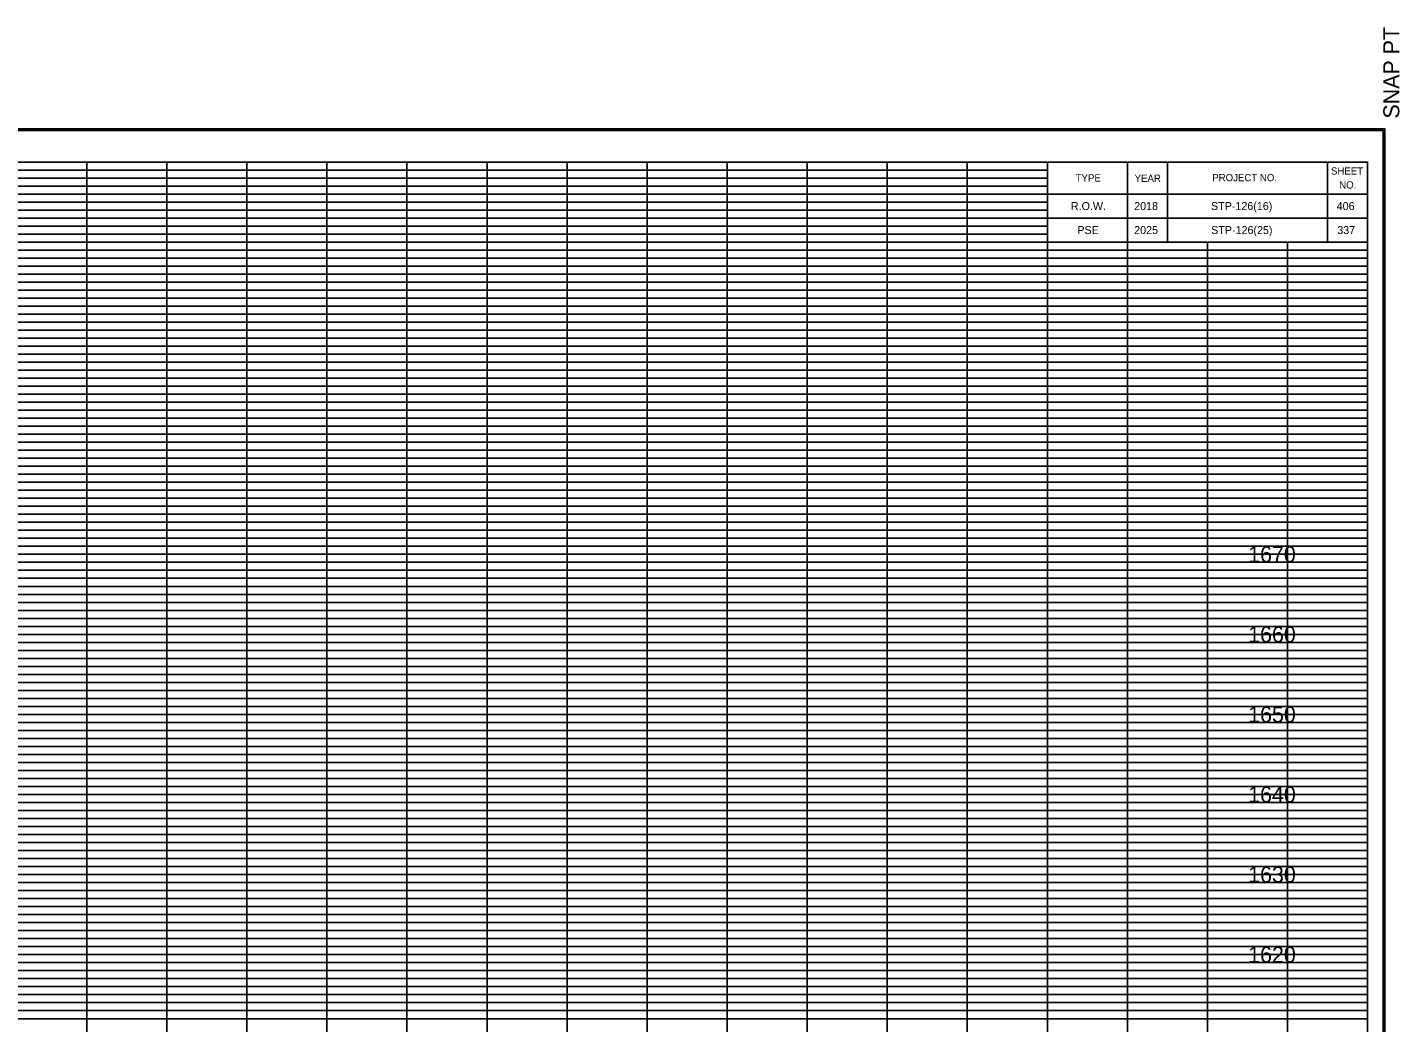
# Model space of a CAD drawing. Extents: x 980 to 1380, y 1248 to 3387.
# Drawn here: x 1152.6 to 1324, y 2452.5 to 2576.8 of the extents above; entities that cross this region are included whole.
import ezdxf

# ---------------------------------------------------------------- set-up
doc = ezdxf.new("R2010")
doc.units = 0
for name, color, linetype in [('DESIGN - SCRATCH - User 1', 7, 'Continuous'), ('DESIGN - SHEET - Corner Text', 7, 'Continuous'), ('DESIGN - SHEET - Light Grid', 7, 'Continuous'), ('DESIGN - SHEET - Linework', 7, 'Continuous'), ('DESIGN - SHEET - Plot Shape', 7, 'Continuous'), ('DESIGN - TYPICAL - Text', 7, 'Continuous')]:
    doc.layers.add(name, color=color, linetype=linetype)

# ---------------------------------------------------------------- blocks, each defined once
blk = doc.blocks.new('XSTSHT')
at = {"layer": 'DESIGN - SCRATCH - User 1'}
for p, q in [((28.5, 20.45), (28.5, 20.45)), ((29.24, 20.45), (29.24, 20.45)), ((30.49, 20.45), (30.49, 20.45)), ((31.74, 20.45), (31.74, 20.45)), ((28.5, 20.15), (28.5, 20.15)), ((29.24, 20.15), (29.24, 20.15)), ((30.49, 20.15), (30.49, 20.15)), ((31.74, 20.15), (31.74, 20.15))]:
    blk.add_line(p, q, dxfattribs=at)
at = {"layer": 'DESIGN - SHEET - Light Grid'}
for p, q in [((8, 20.9), (16, 20.9)), ((8, 20.8), (16, 20.8)), ((16, 20.9), (24, 20.9)), ((16, 20.8), (24, 20.8)), ((24, 20.9), (28, 20.9)), ((24, 20.8), (28, 20.8)), ((8, 20.7), (16, 20.7)), ((8, 20.6), (16, 20.6)), ((16, 20.7), (24, 20.7)), ((16, 20.6), (24, 20.6)), ((24, 20.7), (28, 20.7)), ((24, 20.6), (28, 20.6)), ((8, 20.5), (16, 20.5)), ((8, 20.4), (16, 20.4)), ((16, 20.5), (24, 20.5)), ((16, 20.4), (24, 20.4)), ((24, 20.5), (28, 20.5)), ((24, 20.4), (28, 20.4)), ((8, 20.3), (16, 20.3)), ((16, 20.3), (24, 20.3)), ((24, 20.3), (28, 20.3)), ((8, 20.2), (16, 20.2)), ((8, 20.1), (16, 20.1)), ((16, 20.2), (24, 20.2)), ((16, 20.1), (24, 20.1)), ((24, 20.2), (28, 20.2)), ((24, 20.1), (28, 20.1)), ((8, 19.9), (16, 19.9)), ((16, 19.9), (24, 19.9)), ((24, 19.9), (32, 19.9)), ((8, 19.8), (16, 19.8)), ((16, 19.8), (24, 19.8)), ((24, 19.8), (32, 19.8)), ((8, 19.7), (16, 19.7)), ((8, 19.6), (16, 19.6)), ((16, 19.7), (24, 19.7)), ((16, 19.6), (24, 19.6)), ((24, 19.7), (32, 19.7)), ((24, 19.6), (32, 19.6)), ((8, 19.5), (16, 19.5)), ((8, 19.4), (16, 19.4)), ((16, 19.5), (24, 19.5)), ((16, 19.4), (24, 19.4)), ((24, 19.5), (32, 19.5)), ((24, 19.4), (32, 19.4)), ((8, 19.3), (16, 19.3)), ((8, 19.2), (16, 19.2)), ((16, 19.3), (24, 19.3)), ((16, 19.2), (24, 19.2)), ((24, 19.3), (32, 19.3)), ((24, 19.2), (32, 19.2)), ((8, 19.1), (16, 19.1)), ((16, 19.1), (24, 19.1)), ((24, 19.1), (32, 19.1)), ((8, 18.9), (16, 18.9)), ((16, 18.9), (24, 18.9)), ((24, 18.9), (32, 18.9)), ((8, 18.8), (16, 18.8)), ((8, 18.7), (16, 18.7)), ((16, 18.8), (24, 18.8)), ((16, 18.7), (24, 18.7)), ((24, 18.8), (32, 18.8)), ((24, 18.7), (32, 18.7)), ((8, 18.6), (16, 18.6)), ((16, 18.6), (24, 18.6)), ((24, 18.6), (32, 18.6)), ((8, 18.5), (16, 18.5)), ((8, 18.4), (16, 18.4)), ((16, 18.5), (24, 18.5)), ((16, 18.4), (24, 18.4)), ((24, 18.5), (32, 18.5)), ((24, 18.4), (32, 18.4)), ((8, 18.3), (16, 18.3)), ((8, 18.2), (16, 18.2)), ((16, 18.3), (24, 18.3)), ((16, 18.2), (24, 18.2)), ((24, 18.3), (32, 18.3)), ((24, 18.2), (32, 18.2)), ((8, 18.1), (16, 18.1)), ((16, 18.1), (24, 18.1)), ((24, 18.1), (32, 18.1)), ((8, 17.9), (16, 17.9)), ((16, 17.9), (24, 17.9)), ((24, 17.9), (32, 17.9)), ((8, 17.8), (16, 17.8)), ((8, 17.7), (16, 17.7)), ((16, 17.8), (24, 17.8)), ((16, 17.7), (24, 17.7)), ((24, 17.8), (32, 17.8)), ((24, 17.7), (32, 17.7)), ((8, 17.6), (16, 17.6)), ((8, 17.5), (16, 17.5)), ((16, 17.6), (24, 17.6)), ((16, 17.5), (24, 17.5)), ((24, 17.6), (32, 17.6)), ((24, 17.5), (32, 17.5)), ((8, 17.4), (16, 17.4)), ((16, 17.4), (24, 17.4)), ((24, 17.4), (32, 17.4)), ((8, 17.3), (16, 17.3)), ((8, 17.2), (16, 17.2)), ((16, 17.3), (24, 17.3)), ((16, 17.2), (24, 17.2)), ((24, 17.3), (32, 17.3)), ((24, 17.2), (32, 17.2)), ((8, 17.1), (16, 17.1)), ((16, 17.1), (24, 17.1)), ((24, 17.1), (32, 17.1)), ((8, 16.9), (16, 16.9)), ((8, 16.8), (16, 16.8)), ((16, 16.9), (24, 16.9)), ((16, 16.8), (24, 16.8)), ((24, 16.9), (32, 16.9)), ((24, 16.8), (32, 16.8)), ((8, 16.7), (16, 16.7)), ((16, 16.7), (24, 16.7)), ((24, 16.7), (32, 16.7)), ((8, 16.6), (16, 16.6)), ((8, 16.5), (16, 16.5)), ((16, 16.6), (24, 16.6)), ((16, 16.5), (24, 16.5)), ((24, 16.6), (32, 16.6)), ((24, 16.5), (32, 16.5)), ((8, 16.4), (16, 16.4)), ((8, 16.3), (16, 16.3)), ((16, 16.4), (24, 16.4)), ((16, 16.3), (24, 16.3)), ((24, 16.4), (32, 16.4)), ((24, 16.3), (32, 16.3)), ((8, 16.2), (16, 16.2)), ((16, 16.2), (24, 16.2)), ((24, 16.2), (32, 16.2)), ((8, 16.1), (16, 16.1)), ((16, 16.1), (24, 16.1)), ((24, 16.1), (32, 16.1)), ((8, 15.9), (16, 15.9)), ((8, 15.8), (16, 15.8)), ((16, 15.9), (24, 15.9)), ((16, 15.8), (24, 15.8)), ((24, 15.9), (32, 15.9)), ((24, 15.8), (32, 15.8)), ((8, 15.7), (16, 15.7)), ((8, 15.6), (16, 15.6)), ((16, 15.7), (24, 15.7)), ((16, 15.6), (24, 15.6)), ((24, 15.7), (32, 15.7)), ((24, 15.6), (32, 15.6)), ((8, 15.5), (16, 15.5)), ((16, 15.5), (24, 15.5)), ((24, 15.5), (32, 15.5)), ((8, 15.4), (16, 15.4)), ((8, 15.3), (16, 15.3)), ((16, 15.4), (24, 15.4)), ((16, 15.3), (24, 15.3)), ((24, 15.4), (32, 15.4)), ((24, 15.3), (32, 15.3)), ((8, 15.2), (16, 15.2)), ((8, 15.1), (16, 15.1)), ((16, 15.2), (24, 15.2)), ((16, 15.1), (24, 15.1)), ((24, 15.2), (32, 15.2)), ((24, 15.1), (32, 15.1)), ((8, 14.9), (16, 14.9)), ((8, 14.8), (16, 14.8)), ((16, 14.9), (24, 14.9)), ((16, 14.8), (24, 14.8)), ((24, 14.9), (32, 14.9)), ((24, 14.8), (32, 14.8)), ((8, 14.7), (16, 14.7)), ((8, 14.6), (16, 14.6)), ((16, 14.7), (24, 14.7)), ((16, 14.6), (24, 14.6)), ((24, 14.7), (32, 14.7)), ((24, 14.6), (32, 14.6)), ((8, 14.5), (16, 14.5)), ((8, 14.4), (16, 14.4)), ((16, 14.5), (24, 14.5)), ((16, 14.4), (24, 14.4)), ((24, 14.5), (32, 14.5)), ((24, 14.4), (32, 14.4)), ((8, 14.3), (16, 14.3)), ((16, 14.3), (24, 14.3)), ((24, 14.3), (32, 14.3)), ((8, 14.2), (16, 14.2)), ((8, 14.1), (16, 14.1)), ((16, 14.2), (24, 14.2)), ((16, 14.1), (24, 14.1)), ((24, 14.2), (32, 14.2)), ((24, 14.1), (32, 14.1)), ((8, 13.9), (16, 13.9)), ((16, 13.9), (24, 13.9)), ((24, 13.9), (32, 13.9)), ((8, 13.8), (16, 13.8)), ((16, 13.8), (24, 13.8)), ((24, 13.8), (32, 13.8)), ((8, 13.7), (16, 13.7)), ((8, 13.6), (16, 13.6)), ((16, 13.7), (24, 13.7)), ((16, 13.6), (24, 13.6)), ((24, 13.7), (32, 13.7)), ((24, 13.6), (32, 13.6)), ((8, 13.5), (16, 13.5)), ((8, 13.4), (16, 13.4)), ((16, 13.5), (24, 13.5)), ((16, 13.4), (24, 13.4)), ((24, 13.5), (32, 13.5)), ((24, 13.4), (32, 13.4)), ((8, 13.3), (16, 13.3)), ((8, 13.2), (16, 13.2)), ((16, 13.3), (24, 13.3)), ((16, 13.2), (24, 13.2)), ((24, 13.3), (32, 13.3)), ((24, 13.2), (32, 13.2)), ((8, 13.1), (16, 13.1)), ((16, 13.1), (24, 13.1)), ((24, 13.1), (32, 13.1)), ((8, 12.9), (16, 12.9)), ((16, 12.9), (24, 12.9)), ((24, 12.9), (32, 12.9)), ((8, 12.8), (16, 12.8)), ((8, 12.7), (16, 12.7)), ((16, 12.8), (24, 12.8)), ((16, 12.7), (24, 12.7)), ((24, 12.8), (32, 12.8)), ((24, 12.7), (32, 12.7)), ((8, 12.6), (16, 12.6)), ((16, 12.6), (24, 12.6)), ((24, 12.6), (32, 12.6)), ((8, 12.5), (16, 12.5)), ((8, 12.4), (16, 12.4)), ((16, 12.5), (24, 12.5)), ((16, 12.4), (24, 12.4)), ((24, 12.5), (32, 12.5)), ((24, 12.4), (32, 12.4)), ((8, 12.3), (16, 12.3)), ((8, 12.2), (16, 12.2)), ((16, 12.3), (24, 12.3)), ((16, 12.2), (24, 12.2)), ((24, 12.3), (32, 12.3)), ((24, 12.2), (32, 12.2)), ((8, 12.1), (16, 12.1)), ((16, 12.1), (24, 12.1)), ((24, 12.1), (32, 12.1)), ((8, 11.9), (16, 11.9)), ((16, 11.9), (24, 11.9)), ((24, 11.9), (32, 11.9)), ((8, 11.8), (16, 11.8)), ((8, 11.7), (16, 11.7)), ((16, 11.8), (24, 11.8)), ((16, 11.7), (24, 11.7)), ((24, 11.8), (32, 11.8)), ((24, 11.7), (32, 11.7)), ((8, 11.6), (16, 11.6)), ((8, 11.5), (16, 11.5)), ((16, 11.6), (24, 11.6)), ((16, 11.5), (24, 11.5)), ((24, 11.6), (32, 11.6)), ((24, 11.5), (32, 11.5)), ((8, 11.4), (16, 11.4)), ((16, 11.4), (24, 11.4)), ((24, 11.4), (32, 11.4)), ((8, 11.3), (16, 11.3)), ((8, 11.2), (16, 11.2)), ((16, 11.3), (24, 11.3)), ((16, 11.2), (24, 11.2)), ((24, 11.3), (32, 11.3)), ((24, 11.2), (32, 11.2)), ((8, 11.1), (16, 11.1)), ((16, 11.1), (24, 11.1)), ((24, 11.1), (32, 11.1)), ((8, 10.9), (16, 10.9)), ((8, 10.8), (16, 10.8)), ((16, 10.9), (24, 10.9)), ((16, 10.8), (24, 10.8)), ((24, 10.9), (32, 10.9)), ((24, 10.8), (32, 10.8)), ((8, 10.7), (16, 10.7)), ((16, 10.7), (24, 10.7)), ((24, 10.7), (32, 10.7)), ((8, 10.6), (16, 10.6)), ((8, 10.5), (16, 10.5)), ((16, 10.6), (24, 10.6)), ((16, 10.5), (24, 10.5)), ((24, 10.6), (32, 10.6)), ((24, 10.5), (32, 10.5)), ((8, 10.4), (16, 10.4)), ((8, 10.3), (16, 10.3)), ((16, 10.4), (24, 10.4)), ((16, 10.3), (24, 10.3)), ((24, 10.4), (32, 10.4)), ((24, 10.3), (32, 10.3))]:
    blk.add_line(p, q, dxfattribs=at)
at = {"layer": 'DESIGN - SHEET - Linework'}
for p, q in [((-1.823, 21.414), (32.217, 21.414)), ((32.217, 21.414), (32.217, -0.414)), ((16, 0), (16, 21)), ((17, 0), (17, 21)), ((18, 0), (18, 21)), ((19, 0), (19, 21)), ((20, 0), (20, 21)), ((21, 0), (21, 21)), ((22, 0), (22, 21)), ((23, 0), (23, 21)), ((24, 0), (24, 21)), ((25, 0), (25, 21)), ((26, 0), (26, 21)), ((27, 0), (27, 21)), ((0, 20), (28, 20)), ((28, 0), (28, 20)), ((29, 0), (29, 20)), ((30, 0), (30, 20)), ((31, 0), (31, 20)), ((0, 19), (32, 19)), ((0, 18), (32, 18)), ((0, 17), (32, 17)), ((0, 16), (32, 16)), ((0, 15), (32, 15)), ((0, 14), (32, 14)), ((0, 13), (32, 13)), ((0, 12), (32, 12)), ((0, 11), (32, 11))]:
    blk.add_line(p, q, dxfattribs=at)
for points in [[(0, 21), (0, 0), (32, 0), (32, 21), (0, 21)], [(28, 21), (28, 20), (32, 20), (32, 21), (31.5, 21), (31.5, 20), (29.5, 20), (29.5, 21), (29, 21), (29, 20), (32, 20), (28, 20), (28, 20.3), (32, 20.3), (32, 20.6), (28, 20.6)]]:
    blk.add_lwpolyline(points, dxfattribs=at)
at = {"layer": 'DESIGN - SHEET - Plot Shape'}
for points in [[(-1.803, 21.394), (32.197, 21.394), (32.197, -0.394), (-1.803, -0.394)], [(-0.85, 21), (32, 21), (32, -0.25), (-0.85, -0.25)]]:
    blk.add_lwpolyline(points, close=True, dxfattribs=at)
at = {"layer": 'DESIGN - SHEET - Corner Text'}
blk.add_text('  SNAP PT', height=0.2, rotation=90, dxfattribs=at).set_placement((32.397, 21.394))
for s, p in [('SHEET', (31.543, 20.843)), ('TYPE', (28.354, 20.756)), ('YEAR', (29.09, 20.752)), ('PROJECT NO.', (30.06, 20.76)), ('NO.', (31.646, 20.669))]:
    blk.add_text(s, height=0.09, dxfattribs=at).set_placement(p)

msp = doc.modelspace()

# ---------------------------------------------------------------- linework, layer by layer
at = {"layer": 'DESIGN - SHEET - Plot Shape'}
msp.add_lwpolyline([(991.5, 2347.5), (1320, 2347.5), (1320, 2560), (991.5, 2560)], close=True, dxfattribs=at)

# ---------------------------------------------------------------- block references
at = {"layer": 'DESIGN - TYPICAL - Text', "xscale": 10, "yscale": 10}
msp.add_blockref('XSTSHT', (1000, 2350), dxfattribs=at)

# ---------------------------------------------------------------- texts
at = {"layer": 'DESIGN - SHEET - Corner Text'}
for s, p in [('R.O.W.', (1282.94, 2554)), ('2018', (1290.85, 2554)), ('STP-126(16)', (1300.45, 2554)), ('406', (1316.15, 2554)), ('PSE', (1283.75, 2551)), ('2025', (1290.85, 2551)), ('STP-126(25)', (1300.47, 2551)), ('337', (1316.22, 2551))]:
    msp.add_text(s, height=1, dxfattribs=at).set_placement(p)
at = {"layer": 'DESIGN - TYPICAL - Text'}
for s, p in [('     1670     ', (1301.37, 2510)), ('     1660     ', (1301.37, 2500)), ('     1650     ', (1301.37, 2490)), ('     1640     ', (1301.37, 2480)), ('     1630     ', (1301.37, 2470)), ('     1620     ', (1301.37, 2460))]:
    msp.add_text(s, height=2, dxfattribs=at).set_placement(p)

doc.saveas('drawing.dxf')
